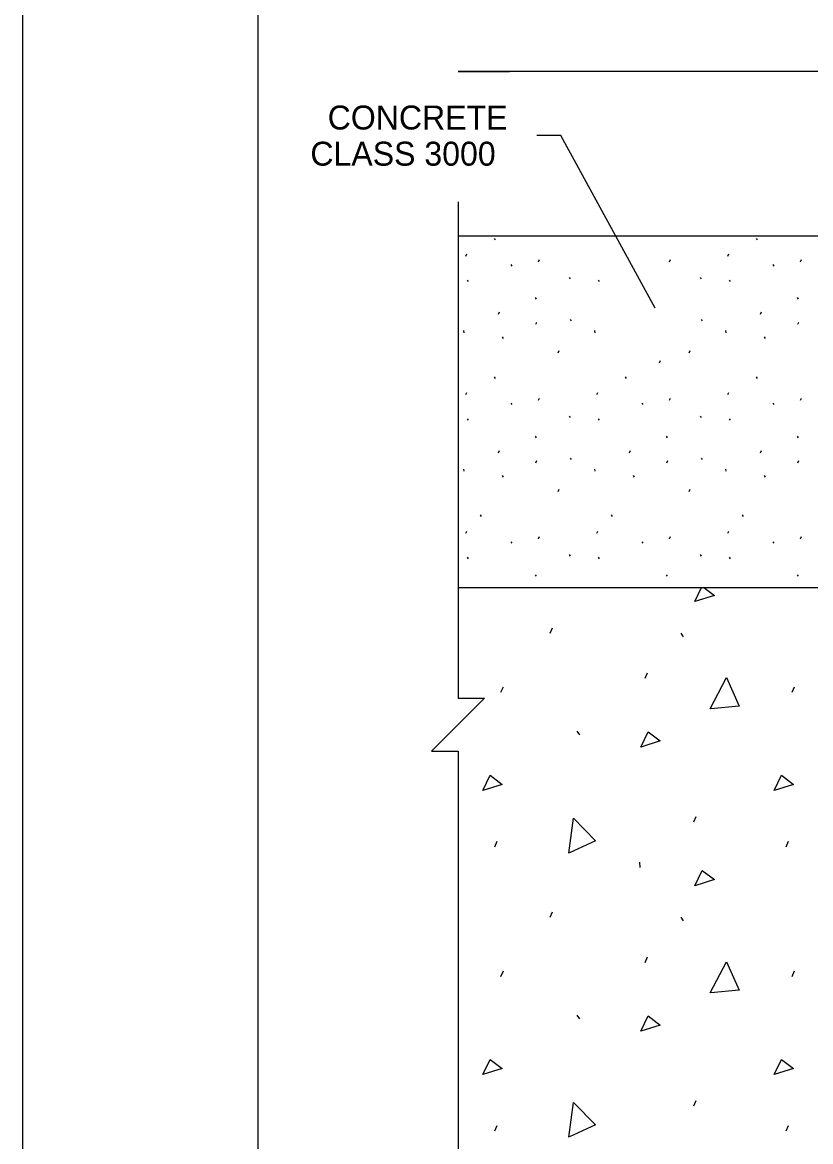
# Model space of a CAD drawing. Extents: x 99988 to 100172, y 99995 to 100047.
# Drawn here: x 99999.312 to 100001.615, y 100005.469 to 100008.738 of the extents above; entities that cross this region are included whole.
import ezdxf

# ---------------------------------------------------------------- set-up
doc = ezdxf.new("R2010")
doc.units = 0
for name, color, linetype in [('Level 1', 7, 'Continuous'), ('Level 15', 7, 'Continuous'), ('Level 2', 7, 'Continuous'), ('Level 20', 7, 'Continuous'), ('Level 3', 7, 'Continuous'), ('SH_GI_PlotLimits', 7, 'Continuous'), ('SH_GI_SheetBorder', 7, 'Continuous')]:
    doc.layers.add(name, color=color, linetype=linetype)

msp = doc.modelspace()

# ---------------------------------------------------------------- linework, layer by layer
at = {"layer": 'Level 1'}
msp.add_line((100000.585, 100008.1139), (100009.7707, 100008.1139), dxfattribs=at)
at = {"layer": 'Level 15'}
for p, q in [((100002.8228, 100008.5939), (100000.585, 100008.5939)), ((100000.585, 100008.5939), (100000.66, 100008.5939)), ((100000.66, 100008.5939), (100000.735, 100008.5939))]:
    msp.add_line(p, q, dxfattribs=at)
for points in [[(100001.161, 100007.903), (100000.8855, 100008.407), (100000.8155, 100008.407)], [(100000.585, 100008.2139), (100000.585, 100006.7638), (100000.6625, 100006.7638), (100000.5076, 100006.609), (100000.585, 100006.609), (100000.585, 100005.1589)]]:
    msp.add_lwpolyline(points, dxfattribs=at)
at = {"layer": 'Level 2'}
msp.add_line((100000.585, 100007.0869), (100009.7707, 100007.0869), dxfattribs=at)
at = {"layer": 'Level 3'}
for p, q in [((100000.6907, 100008.1069), (100000.6936, 100008.1026)), ((100001.456, 100008.1069), (100001.4589, 100008.1026)), ((100000.6073, 100008.0553), (100000.6102, 100008.0617)), ((100001.3726, 100008.0553), (100001.3755, 100008.0617)), ((100000.739, 100008.0303), (100000.7419, 100008.026)), ((100000.8195, 100008.0387), (100000.8224, 100008.0452)), ((100001.2021, 100008.0387), (100001.205, 100008.0452)), ((100001.5043, 100008.0303), (100001.5071, 100008.026)), ((100001.5848, 100008.0387), (100001.5876, 100008.0452)), ((100000.9094, 100007.9927), (100000.9123, 100007.9884)), ((100001.292, 100007.9927), (100001.2949, 100007.9884)), ((100000.6118, 100007.9849), (100000.6146, 100007.9806)), ((100000.9944, 100007.9849), (100000.9973, 100007.9806)), ((100001.377, 100007.9849), (100001.3799, 100007.9806)), ((100000.8099, 100007.9338), (100000.8128, 100007.9295)), ((100001.5752, 100007.9338), (100001.5781, 100007.9295)), ((100000.703, 100007.8855), (100000.7058, 100007.892)), ((100001.4682, 100007.8855), (100001.4711, 100007.892)), ((100000.8123, 100007.856), (100000.8152, 100007.8625)), ((100000.9121, 100007.87), (100000.915, 100007.8656)), ((100001.2947, 100007.87), (100001.2976, 100007.8656)), ((100001.5776, 100007.856), (100001.5805, 100007.8625)), ((100000.6007, 100007.8379), (100000.6014, 100007.8315)), ((100000.9833, 100007.8379), (100000.984, 100007.8315)), ((100001.3659, 100007.8379), (100001.3667, 100007.8315)), ((100000.7134, 100007.8189), (100000.7163, 100007.8146)), ((100001.4787, 100007.8189), (100001.4816, 100007.8146)), ((100000.8778, 100007.7726), (100000.8806, 100007.779)), ((100001.2604, 100007.7726), (100001.2633, 100007.779)), ((100001.1735, 100007.7438), (100001.1764, 100007.7503)), ((100000.6907, 100007.7022), (100000.6936, 100007.6979)), ((100001.0734, 100007.7022), (100001.0762, 100007.6979)), ((100001.456, 100007.7022), (100001.4589, 100007.6979)), ((100000.6073, 100007.6505), (100000.6102, 100007.657)), ((100000.8195, 100007.634), (100000.8224, 100007.6405)), ((100000.99, 100007.6505), (100000.9928, 100007.657)), ((100001.2021, 100007.634), (100001.205, 100007.6405)), ((100001.3726, 100007.6505), (100001.3755, 100007.657)), ((100001.5848, 100007.634), (100001.5876, 100007.6405)), ((100000.739, 100007.6256), (100000.7419, 100007.6213)), ((100001.1216, 100007.6256), (100001.1245, 100007.6213)), ((100001.5043, 100007.6256), (100001.5071, 100007.6213)), ((100000.6118, 100007.5802), (100000.6146, 100007.5759)), ((100000.9094, 100007.588), (100000.9123, 100007.5836)), ((100000.9944, 100007.5802), (100000.9973, 100007.5759)), ((100001.292, 100007.588), (100001.2949, 100007.5836)), ((100001.377, 100007.5802), (100001.3799, 100007.5759)), ((100000.8099, 100007.5291), (100000.8128, 100007.5248)), ((100001.1926, 100007.5291), (100001.1954, 100007.5248)), ((100001.5752, 100007.5291), (100001.5781, 100007.5248)), ((100000.703, 100007.4808), (100000.7058, 100007.4873)), ((100000.9121, 100007.4652), (100000.915, 100007.4609)), ((100001.0856, 100007.4808), (100001.0885, 100007.4873)), ((100001.2947, 100007.4652), (100001.2976, 100007.4609)), ((100001.4682, 100007.4808), (100001.4711, 100007.4873)), ((100000.6007, 100007.4332), (100000.6014, 100007.4268)), ((100000.8123, 100007.4513), (100000.8152, 100007.4578)), ((100000.9833, 100007.4332), (100000.984, 100007.4268)), ((100001.1949, 100007.4513), (100001.1978, 100007.4578)), ((100001.3659, 100007.4332), (100001.3667, 100007.4268)), ((100001.5776, 100007.4513), (100001.5805, 100007.4578)), ((100000.7134, 100007.4142), (100000.7163, 100007.4098)), ((100001.0961, 100007.4142), (100001.0989, 100007.4098)), ((100001.4787, 100007.4142), (100001.4816, 100007.4098)), ((100000.8778, 100007.3679), (100000.8806, 100007.3743)), ((100001.2604, 100007.3679), (100001.2633, 100007.3743)), ((100000.6498, 100007.2991), (100000.6526, 100007.2948)), ((100001.0324, 100007.2991), (100001.0353, 100007.2948)), ((100001.415, 100007.2991), (100001.4179, 100007.2948)), ((100000.6073, 100007.2458), (100000.6102, 100007.2523)), ((100000.8195, 100007.2293), (100000.8224, 100007.2358)), ((100000.99, 100007.2458), (100000.9928, 100007.2523)), ((100001.2021, 100007.2293), (100001.205, 100007.2358)), ((100001.3726, 100007.2458), (100001.3755, 100007.2523)), ((100001.5848, 100007.2293), (100001.5876, 100007.2358)), ((100000.739, 100007.2209), (100000.7419, 100007.2166)), ((100001.1216, 100007.2209), (100001.1245, 100007.2166)), ((100001.5043, 100007.2209), (100001.5071, 100007.2166)), ((100000.6118, 100007.1755), (100000.6146, 100007.1711)), ((100000.9094, 100007.1833), (100000.9123, 100007.1789)), ((100000.9944, 100007.1755), (100000.9973, 100007.1711)), ((100001.292, 100007.1833), (100001.2949, 100007.1789)), ((100001.377, 100007.1755), (100001.3799, 100007.1711)), ((100000.8099, 100007.1244), (100000.8128, 100007.1201)), ((100001.1926, 100007.1244), (100001.1954, 100007.1201)), ((100001.5752, 100007.1244), (100001.5781, 100007.1201)), ((100000.8539, 100006.9538), (100000.861, 100006.9698)), ((100001.2358, 100006.9538), (100001.2429, 100006.9432)), ((100001.131, 100006.8222), (100001.1381, 100006.8382)), ((100000.7101, 100006.7813), (100000.7172, 100006.7973)), ((100001.5608, 100006.7813), (100001.5679, 100006.7973)), ((100000.9321, 100006.6677), (100000.9392, 100006.657)), ((100001.2731, 100006.403), (100001.2802, 100006.419)), ((100000.6923, 100006.3302), (100000.6994, 100006.3462)), ((100001.5431, 100006.3302), (100001.5502, 100006.3462)), ((100001.1146, 100006.2856), (100001.1163, 100006.2696)), ((100000.8539, 100006.1242), (100000.861, 100006.1402)), ((100001.2358, 100006.1242), (100001.2429, 100006.1135)), ((100001.131, 100005.9925), (100001.1381, 100006.0085)), ((100000.7101, 100005.9517), (100000.7172, 100005.9677)), ((100001.5608, 100005.9517), (100001.5679, 100005.9677)), ((100000.9321, 100005.838), (100000.9392, 100005.8274)), ((100001.2731, 100005.5734), (100001.2802, 100005.5894)), ((100000.6923, 100005.5006), (100000.6994, 100005.5166)), ((100001.5431, 100005.5006), (100001.5502, 100005.5166))]:
    msp.add_line(p, q, dxfattribs=at)
for points in [[(100001.3028, 100007.0869), (100001.3335, 100007.0639), (100001.2767, 100007.0462)], [(100001.2767, 100007.0462), (100001.2962, 100007.0869)], [(100001.3211, 100006.7334), (100001.369, 100006.824), (100001.4063, 100006.7405), (100001.3228, 100006.7334)], [(100001.1186, 100006.6215), (100001.1399, 100006.6659), (100001.1754, 100006.6392), (100001.1186, 100006.6215)], [(100000.6571, 100006.4945), (100000.6784, 100006.5389), (100000.714, 100006.5123), (100000.6571, 100006.4945)], [(100001.5079, 100006.4945), (100001.5292, 100006.5389), (100001.5647, 100006.5123), (100001.5079, 100006.4945)], [(100000.9084, 100006.3118), (100000.9225, 100006.4133), (100000.9861, 100006.3477), (100000.91, 100006.3124)], [(100001.2767, 100006.2165), (100001.298, 100006.261), (100001.3335, 100006.2343), (100001.2767, 100006.2165)], [(100001.3211, 100005.9037), (100001.369, 100005.9943), (100001.4063, 100005.9109), (100001.3228, 100005.9037)], [(100001.1186, 100005.7919), (100001.1399, 100005.8363), (100001.1754, 100005.8096), (100001.1186, 100005.7919)], [(100000.6571, 100005.6649), (100000.6784, 100005.7093), (100000.714, 100005.6827), (100000.6571, 100005.6649)], [(100001.5079, 100005.6649), (100001.5292, 100005.7093), (100001.5647, 100005.6827), (100001.5079, 100005.6649)], [(100000.9084, 100005.4822), (100000.9225, 100005.5837), (100000.9861, 100005.518), (100000.91, 100005.4828)]]:
    msp.add_lwpolyline(points, dxfattribs=at)
at = {"layer": 'SH_GI_PlotLimits'}
msp.add_lwpolyline([(99999.3125, 99999.9375), (100015.8125, 99999.9375), (100015.8125, 100010.4375), (99999.3125, 100010.4375)], close=True, dxfattribs=at)
at = {"layer": 'SH_GI_SheetBorder'}
msp.add_line((100000, 100010.375), (100000, 100000), dxfattribs=at)

# ---------------------------------------------------------------- texts
at = {"layer": 'Level 20'}
for s, p in [('CONCRETE', (100000.2042, 100008.4248)), ('CLASS 3000', (100000.1536, 100008.3192))]:
    msp.add_text(s, height=0.07, dxfattribs=at).set_placement(p)

doc.saveas('drawing.dxf')
